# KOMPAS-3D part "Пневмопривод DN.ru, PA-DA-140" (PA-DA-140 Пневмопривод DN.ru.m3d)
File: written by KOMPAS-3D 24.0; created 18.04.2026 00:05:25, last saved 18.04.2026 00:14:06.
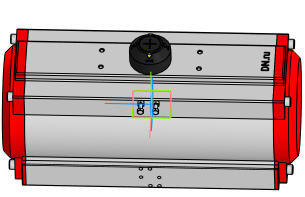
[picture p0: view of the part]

Document properties: Автор: DN.ru; Полное имя файла: C:\Работа\PA-DA-х Пневмопривод DN.ru\140\PA-DA-140 Пневмопривод DN.ru.m3d

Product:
- Part/product: Пневмопривод DN.ru  | designation PA-DA-140
    Масса: 13
    Раздел спецификации: Прочие изделия
    Примечание: D290-00298

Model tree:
1. Операция без истории:1

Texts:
  PA-DA-140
